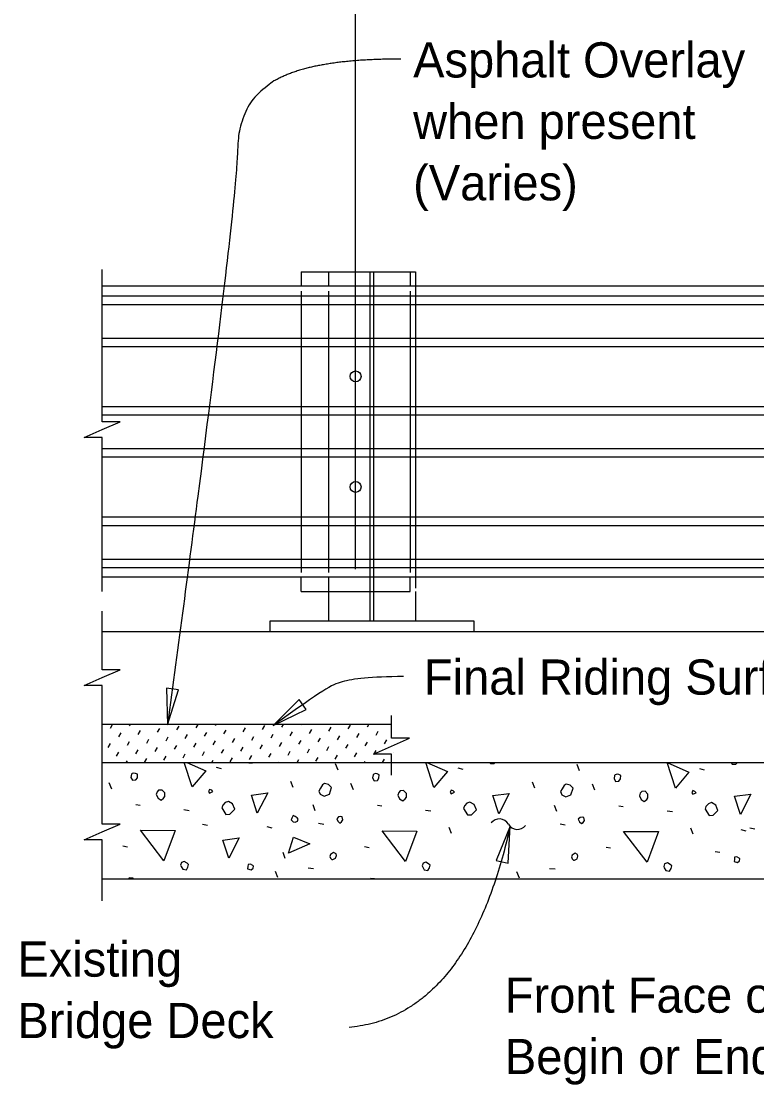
# Model space of a CAD drawing. Extents: x 21587 to 21659.1, y 56113.9 to 56155.9.
# Drawn here: x 21587.2 to 21591.41, y 56132.2 to 56138.3 of the extents above; entities that cross this region are included whole.
import ezdxf

# ---------------------------------------------------------------- set-up
doc = ezdxf.new("R2010")
doc.units = 0
for name, color, linetype in [('AdhocPoint_dp', 7, 'Continuous'), ('Border', 7, 'Continuous'), ('Patterning', 7, 'Continuous'), ('PlotBorder_dp', 7, 'Continuous'), ('SheetBorder_dp', 7, 'Continuous'), ('TextMisc', 7, 'Continuous')]:
    doc.layers.add(name, color=color, linetype=linetype)

msp = doc.modelspace()

# ---------------------------------------------------------------- linework, layer by layer
at = {"layer": 'AdhocPoint_dp'}
for p, q in [((21593.837, 56134.8009), (21587.6633, 56134.8009)), ((21589.3212, 56134.2699), (21587.6633, 56134.2699)), ((21587.6633, 56134.0511), (21593.837, 56134.0511)), ((21587.6633, 56133.3843), (21593.837, 56133.3843))]:
    msp.add_line(p, q, dxfattribs=at)
at = {"layer": 'Border'}
for p, q in [((21588.9596, 56136.8635), (21589.4596, 56136.8635)), ((21588.9596, 56136.8635), (21588.9596, 56136.7802)), ((21599.7592, 56136.7801), (21587.6633, 56136.7801)), ((21587.6633, 56136.7246), (21599.7592, 56136.7246)), ((21587.6633, 56136.6764), (21599.7592, 56136.6764)), ((21587.6633, 56136.4835), (21599.7592, 56136.4835)), ((21587.6633, 56136.4353), (21599.7592, 56136.4353)), ((21587.6633, 56136.0914), (21599.7592, 56136.0914)), ((21587.6633, 56136.0431), (21599.7592, 56136.0431)), ((21587.6633, 56135.8503), (21599.7592, 56135.8503)), ((21587.6633, 56135.8022), (21599.7592, 56135.8022)), ((21587.6633, 56135.4582), (21599.7592, 56135.4582)), ((21587.6633, 56135.41), (21599.7592, 56135.41)), ((21587.6633, 56135.2172), (21599.7592, 56135.2172)), ((21587.6633, 56135.169), (21599.7592, 56135.169)), ((21599.7592, 56135.1134), (21587.6633, 56135.1134)), ((21588.9596, 56135.1135), (21588.9596, 56134.8635)), ((21589.4596, 56135.0302), (21589.4596, 56134.8635)), ((21588.6263, 56134.8635), (21589.7929, 56134.8635)), ((21588.6263, 56134.801), (21588.6263, 56134.8635)), ((21588.9596, 56134.8635), (21589.4596, 56134.8635)), ((21589.7929, 56134.8635), (21589.7929, 56134.801)), ((21588.6263, 56134.801), (21589.7929, 56134.801))]:
    msp.add_line(p, q, dxfattribs=at)
for centre in [(21589.1159, 56136.2634), (21589.1159, 56135.6303)]:
    msp.add_circle(centre, 0.0312, dxfattribs=at)
at = {"layer": 'Patterning'}
for p, q in [((21589.1992, 56134.8635), (21589.1992, 56136.8635)), ((21589.22, 56134.8635), (21589.22, 56136.8635)), ((21589.4596, 56136.8635), (21589.4596, 56135.0505)), ((21588.9596, 56136.7516), (21588.9596, 56135.1398))]:
    msp.add_line(p, q, dxfattribs=at)
at = {"layer": 'PlotBorder_dp'}
msp.add_line((21589.1159, 56135.1581), (21589.1159, 56143.3113), dxfattribs=at)
for points in [[(21587.6633, 56135.0304), (21587.6633, 56135.9136), (21587.5599, 56135.9136), (21587.6633, 56135.9586), (21587.7666, 56136.0036), (21587.6633, 56136.0036), (21587.6633, 56136.8766)], [(21587.6633, 56134.023), (21587.6633, 56134.4931), (21587.5599, 56134.4931), (21587.6633, 56134.5381), (21587.7666, 56134.5831), (21587.6633, 56134.5831), (21587.6633, 56134.9176)], [(21589.3213, 56133.979), (21589.3213, 56134.0999), (21589.2179, 56134.0999), (21589.3213, 56134.1449), (21589.4246, 56134.1899), (21589.3213, 56134.1899), (21589.3213, 56134.3205)], [(21587.6633, 56133.2579), (21587.6633, 56133.6085), (21587.5599, 56133.6085), (21587.6633, 56133.6535), (21587.7666, 56133.6985), (21587.6633, 56133.6985), (21587.6633, 56134.023)]]:
    msp.add_lwpolyline(points, dxfattribs=at)
for points in [[(21588.0386, 56134.2665), (21588.1011, 56134.4682), (21588.0312, 56134.4775)], [(21588.6428, 56134.2633), (21588.8333, 56134.3544), (21588.7927, 56134.4121)], [(21590.0017, 56133.6862), (21589.922, 56133.4906), (21589.9908, 56133.4753)]]:
    msp.add_lwpolyline(points, close=True, dxfattribs=at)
for centre, start, end in [((21589.94, 56133.6681), 30.00813, 141.73535), ((21590.0432, 56133.7277), 210.00813, 321.73535)]:
    msp.add_arc(centre, 0.0596, start, end, dxfattribs=at)
for points, degree in [([(21589.3746, 56138.082), (21588.8608, 56138.082), (21588.4383, 56137.8307), (21588.4383, 56137.2595), (21588.0386, 56134.2665)], 2), ([(21589.3913, 56134.5436), (21589.1979, 56134.5415), (21589.0095, 56134.5211), (21588.9381, 56134.4713), (21588.6427, 56134.2634)], 3), ([(21590.0017, 56133.6862), (21589.758, 56132.5935), (21589.078, 56132.5336)], 2)]:
    msp.add_open_spline(points, degree=degree, dxfattribs=at)
at = {"layer": 'TextMisc'}
for p, q in [((21588.8034, 56136.8635), (21589.4284, 56136.8635)), ((21588.8034, 56136.8635), (21588.8034, 56136.7802)), ((21589.4284, 56136.8635), (21589.4284, 56136.7802)), ((21588.8034, 56136.7516), (21588.8034, 56135.1398)), ((21589.4284, 56136.7516), (21589.4284, 56135.1398)), ((21588.8034, 56135.0302), (21588.8034, 56135.1135)), ((21589.4284, 56135.0302), (21589.4284, 56135.1135)), ((21588.8034, 56135.0302), (21589.4284, 56135.0302)), ((21587.7102, 56134.2474), (21587.7231, 56134.2698)), ((21587.8208, 56134.2604), (21587.8263, 56134.2699)), ((21588.0909, 56134.2375), (21588.1039, 56134.2599)), ((21588.2015, 56134.2504), (21588.2128, 56134.2699)), ((21588.3122, 56134.2634), (21588.3159, 56134.2699)), ((21588.5823, 56134.2405), (21588.5952, 56134.2629)), ((21588.6929, 56134.2535), (21588.7024, 56134.2699)), ((21588.8035, 56134.2664), (21588.8055, 56134.2699)), ((21589.0736, 56134.2435), (21589.0866, 56134.2659)), ((21589.1843, 56134.2565), (21589.192, 56134.2699)), ((21589.2949, 56134.2695), (21589.2952, 56134.2699)), ((21587.759, 56134.1986), (21587.772, 56134.221)), ((21587.8696, 56134.2116), (21587.8826, 56134.234)), ((21587.9803, 56134.2245), (21587.9932, 56134.2469)), ((21588.1397, 56134.1887), (21588.1527, 56134.211)), ((21588.2504, 56134.2016), (21588.2633, 56134.224)), ((21588.361, 56134.2146), (21588.374, 56134.237)), ((21588.4716, 56134.2275), (21588.4846, 56134.2499)), ((21588.5205, 56134.1787), (21588.5334, 56134.2011)), ((21588.6311, 56134.1917), (21588.6441, 56134.2141)), ((21588.7417, 56134.2046), (21588.7547, 56134.227)), ((21588.8524, 56134.2176), (21588.8653, 56134.24)), ((21588.963, 56134.2306), (21588.976, 56134.253)), ((21589.0118, 56134.1817), (21589.0248, 56134.2041)), ((21589.1225, 56134.1947), (21589.1354, 56134.2171)), ((21589.2331, 56134.2077), (21589.2461, 56134.23)), ((21587.6972, 56134.1368), (21587.7102, 56134.1592)), ((21587.8078, 56134.1498), (21587.8208, 56134.1722)), ((21587.9185, 56134.1627), (21587.9314, 56134.1851)), ((21588.0291, 56134.1757), (21588.0421, 56134.1981)), ((21588.0779, 56134.1269), (21588.0909, 56134.1492)), ((21588.1886, 56134.1398), (21588.2015, 56134.1622)), ((21588.2992, 56134.1528), (21588.3122, 56134.1752)), ((21588.4098, 56134.1657), (21588.4228, 56134.1881)), ((21588.4587, 56134.1169), (21588.4716, 56134.1393)), ((21588.5693, 56134.1299), (21588.5823, 56134.1523)), ((21588.6799, 56134.1428), (21588.6929, 56134.1652)), ((21588.7906, 56134.1558), (21588.8035, 56134.1782)), ((21588.9012, 56134.1688), (21588.9142, 56134.1912)), ((21588.95, 56134.1199), (21588.963, 56134.1423)), ((21589.0607, 56134.1329), (21589.0736, 56134.1553)), ((21589.1713, 56134.1459), (21589.1843, 56134.1682)), ((21589.2819, 56134.1588), (21589.2949, 56134.1812)), ((21587.746, 56134.088), (21587.759, 56134.1104)), ((21587.8567, 56134.1009), (21587.8696, 56134.1233)), ((21587.9673, 56134.1139), (21587.9803, 56134.1363)), ((21588.0161, 56134.0651), (21588.0291, 56134.0874)), ((21588.1268, 56134.078), (21588.1397, 56134.1004)), ((21588.2374, 56134.091), (21588.2504, 56134.1134)), ((21588.348, 56134.1039), (21588.361, 56134.1263)), ((21588.3969, 56134.0551), (21588.4098, 56134.0775)), ((21588.5075, 56134.0681), (21588.5205, 56134.0905)), ((21588.6181, 56134.081), (21588.6311, 56134.1034)), ((21588.7288, 56134.094), (21588.7417, 56134.1164)), ((21588.8394, 56134.107), (21588.8524, 56134.1294)), ((21588.8882, 56134.0581), (21588.9012, 56134.0805)), ((21588.9989, 56134.0711), (21589.0118, 56134.0935)), ((21589.1095, 56134.0841), (21589.1225, 56134.1065)), ((21589.2201, 56134.097), (21589.2331, 56134.1194)), ((21589.3308, 56134.11), (21589.3309, 56134.1102)), ((21587.8017, 56134.0509), (21587.8078, 56134.0615)), ((21587.9055, 56134.0521), (21587.9185, 56134.0745)), ((21588.1882, 56134.0509), (21588.1886, 56134.0516)), ((21588.2913, 56134.0509), (21588.2992, 56134.0645)), ((21588.3168, 56134.0238), (21588.3451, 56134.0167)), ((21588.6778, 56134.0509), (21588.6799, 56134.0546)), ((21588.7809, 56134.0509), (21588.7906, 56134.0676)), ((21589.0151, 56134.0079), (21589.001, 56134.0432)), ((21589.1674, 56134.0509), (21589.1713, 56134.0576)), ((21589.2706, 56134.0509), (21589.2819, 56134.0706)), ((21589.7015, 56134.0203), (21589.7298, 56134.0132)), ((21590.3998, 56134.0043), (21590.3856, 56134.0397)), ((21591.0862, 56134.0167), (21591.1145, 56134.0096)), ((21587.7182, 56133.8989), (21587.7041, 56133.9343)), ((21588.7588, 56133.9071), (21588.7446, 56133.9425)), ((21589.1029, 56133.8954), (21589.0887, 56133.9307)), ((21590.1435, 56133.9036), (21590.1293, 56133.9389)), ((21590.4875, 56133.8918), (21590.4734, 56133.9272)), ((21587.8561, 56133.8105), (21587.8808, 56133.807)), ((21588.1319, 56133.7822), (21588.1619, 56133.7769)), ((21588.8843, 56133.7745), (21588.8719, 56133.8081)), ((21589.2408, 56133.807), (21589.2655, 56133.8034)), ((21589.5165, 56133.7787), (21589.5466, 56133.7734)), ((21590.269, 56133.771), (21590.2566, 56133.8046)), ((21590.6254, 56133.8034), (21590.6502, 56133.7999)), ((21590.9012, 56133.7752), (21590.9313, 56133.7699)), ((21588.2388, 56133.6983), (21588.2671, 56133.6913)), ((21588.6068, 56133.6844), (21588.635, 56133.6773)), ((21588.9031, 56133.7027), (21588.9332, 56133.6974)), ((21589.665, 56133.6443), (21589.6526, 56133.6779)), ((21590.2878, 56133.6991), (21590.3178, 56133.6938)), ((21591.0497, 56133.6408), (21591.0373, 56133.6744)), ((21591.3237, 56133.6673), (21591.352, 56133.6603)), ((21591.3761, 56133.6773), (21591.4044, 56133.6702)), ((21587.7818, 56133.5736), (21587.8083, 56133.5683)), ((21588.7128, 56133.5018), (21588.7004, 56133.5354)), ((21589.1665, 56133.5701), (21589.193, 56133.5648)), ((21590.5512, 56133.5666), (21590.5777, 56133.5613)), ((21591.177, 56133.5418), (21591.2035, 56133.5365)), ((21588.6704, 56133.3922), (21588.6563, 56133.4275)), ((21588.843, 56133.4481), (21588.8748, 56133.4446)), ((21590.0551, 56133.3886), (21590.0409, 56133.424)), ((21590.2277, 56133.4446), (21590.2595, 56133.4411))]:
    msp.add_line(p, q, dxfattribs=at)
for points in [[(21588.1796, 56133.9113), (21588.1341, 56134.0509)], [(21588.148, 56134.0509), (21588.2574, 56134.0032), (21588.1796, 56133.9113)], [(21588.5032, 56134.0509), (21588.5042, 56134.0485), (21588.5018, 56134.0509)], [(21588.5042, 56134.0485), (21588.5254, 56134.0485), (21588.5278, 56134.0509)], [(21589.5643, 56133.9077), (21589.5177, 56134.0509)], [(21589.5246, 56134.0509), (21589.642, 56133.9997), (21589.5643, 56133.9077)], [(21589.8864, 56134.0509), (21589.8889, 56134.045), (21589.8854, 56134.0485)], [(21589.8889, 56134.045), (21589.9101, 56134.045), (21589.9161, 56134.0509)], [(21590.9489, 56133.9042), (21590.9012, 56134.0509), (21591.0267, 56133.9961), (21590.9489, 56133.9042)], [(21591.2695, 56134.0509), (21591.2736, 56134.0415), (21591.27, 56134.045)], [(21591.2736, 56134.0415), (21591.2948, 56134.0415), (21591.3043, 56134.0509)], [(21587.8278, 56133.9661), (21587.8366, 56133.9502), (21587.8561, 56133.9519), (21587.8649, 56133.9643), (21587.8667, 56133.9838), (21587.8543, 56133.9891), (21587.8455, 56133.9908), (21587.8349, 56133.9873), (21587.8313, 56133.9838), (21587.8278, 56133.9661)], [(21589.2125, 56133.9625), (21589.2213, 56133.9466), (21589.2408, 56133.9484), (21589.2496, 56133.9608), (21589.2514, 56133.9802), (21589.239, 56133.9855), (21589.2302, 56133.9873), (21589.2195, 56133.9838), (21589.216, 56133.9802), (21589.2125, 56133.9625)], [(21590.5971, 56133.959), (21590.606, 56133.9431), (21590.6254, 56133.9449), (21590.6343, 56133.9572), (21590.636, 56133.9767), (21590.6237, 56133.982), (21590.6148, 56133.9838), (21590.6042, 56133.9802), (21590.6007, 56133.9767), (21590.5971, 56133.959)], [(21588.2786, 56133.8759), (21588.298, 56133.8848), (21588.291, 56133.8918), (21588.2786, 56133.8971), (21588.2733, 56133.8848), (21588.2786, 56133.8759)], [(21588.9126, 56133.87), (21588.9356, 56133.8576), (21588.9656, 56133.87), (21588.978, 56133.9071), (21588.9603, 56133.9248), (21588.9373, 56133.9301), (21588.9267, 56133.923), (21588.9143, 56133.9036), (21588.9055, 56133.8877), (21588.9126, 56133.87)], [(21590.2973, 56133.8665), (21590.3202, 56133.8541), (21590.3503, 56133.8665), (21590.3627, 56133.9036), (21590.345, 56133.9213), (21590.322, 56133.9266), (21590.3114, 56133.9195), (21590.299, 56133.9), (21590.2902, 56133.8841), (21590.2973, 56133.8665)], [(21587.9728, 56133.8671), (21587.9834, 56133.8459), (21588.001, 56133.8353), (21588.0152, 56133.8459), (21588.0222, 56133.8565), (21588.0222, 56133.8777), (21588.0063, 56133.8936), (21587.9869, 56133.8918), (21587.9781, 56133.883), (21587.9728, 56133.8671)], [(21588.552, 56133.7604), (21588.5184, 56133.8647), (21588.6121, 56133.8771), (21588.552, 56133.7604)], [(21589.3574, 56133.8635), (21589.368, 56133.8423), (21589.3857, 56133.8317), (21589.3999, 56133.8423), (21589.4069, 56133.8529), (21589.4069, 56133.8742), (21589.391, 56133.8901), (21589.3716, 56133.8883), (21589.3627, 56133.8795), (21589.3574, 56133.8635)], [(21589.6633, 56133.8724), (21589.6827, 56133.8812), (21589.6756, 56133.8883), (21589.6633, 56133.8936), (21589.6579, 56133.8812), (21589.6633, 56133.8724)], [(21589.9366, 56133.7569), (21589.903, 56133.8612), (21589.9967, 56133.8735), (21589.9366, 56133.7569)], [(21590.7421, 56133.86), (21590.7527, 56133.8388), (21590.7704, 56133.8282), (21590.7845, 56133.8388), (21590.7916, 56133.8494), (21590.7916, 56133.8706), (21590.7757, 56133.8865), (21590.7562, 56133.8848), (21590.7474, 56133.8759), (21590.7421, 56133.86)], [(21591.0479, 56133.8689), (21591.0674, 56133.8777), (21591.0603, 56133.8848), (21591.0479, 56133.8901), (21591.0426, 56133.8777), (21591.0479, 56133.8689)], [(21591.3213, 56133.7533), (21591.2877, 56133.8576), (21591.3814, 56133.87), (21591.3213, 56133.7533)], [(21588.3493, 56133.7911), (21588.3723, 56133.7539), (21588.3952, 56133.7557), (21588.4041, 56133.7646), (21588.4235, 56133.784), (21588.4112, 56133.814), (21588.3864, 56133.8282), (21588.3687, 56133.8211), (21588.3546, 56133.807), (21588.3493, 56133.7911)], [(21589.734, 56133.7875), (21589.7569, 56133.7504), (21589.7799, 56133.7522), (21589.7888, 56133.761), (21589.8082, 56133.7805), (21589.7958, 56133.8105), (21589.7711, 56133.8247), (21589.7534, 56133.8176), (21589.7393, 56133.8034), (21589.734, 56133.7875)], [(21591.1186, 56133.784), (21591.1416, 56133.7469), (21591.1646, 56133.7486), (21591.1734, 56133.7575), (21591.1929, 56133.7769), (21591.1805, 56133.807), (21591.1558, 56133.8211), (21591.1381, 56133.814), (21591.1239, 56133.7999), (21591.1186, 56133.784)], [(21588.7577, 56133.7114), (21588.7701, 56133.7096), (21588.7824, 56133.7149), (21588.786, 56133.7256), (21588.7807, 56133.7344), (21588.7701, 56133.7415), (21588.7577, 56133.7468), (21588.7506, 56133.7326), (21588.7471, 56133.722), (21588.7577, 56133.7114)], [(21589.0145, 56133.7151), (21589.0251, 56133.7044), (21589.0357, 56133.7115), (21589.0428, 56133.7221), (21589.0392, 56133.7398), (21589.0304, 56133.7416), (21589.018, 56133.7398), (21589.0074, 56133.7292), (21589.0145, 56133.7151)], [(21590.3992, 56133.7115), (21590.4098, 56133.7009), (21590.4204, 56133.708), (21590.4274, 56133.7186), (21590.4239, 56133.7363), (21590.4151, 56133.738), (21590.4027, 56133.7363), (21590.3921, 56133.7257), (21590.3992, 56133.7115)], [(21588.0169, 56133.487), (21587.8826, 56133.6638), (21588.0824, 56133.662), (21588.0169, 56133.487)], [(21589.4016, 56133.4835), (21589.2673, 56133.6603), (21589.467, 56133.6585), (21589.4016, 56133.4835)], [(21590.7863, 56133.4799), (21590.652, 56133.6567), (21590.8517, 56133.655), (21590.7863, 56133.4799)], [(21588.3887, 56133.5022), (21588.3551, 56133.6065), (21588.4488, 56133.6188), (21588.3887, 56133.5022)], [(21588.7316, 56133.5312), (21588.7599, 56133.6231), (21588.8536, 56133.586), (21588.7316, 56133.5312)], [(21588.9791, 56133.4959), (21588.9862, 56133.4959), (21589.0003, 56133.5029), (21589.0056, 56133.5188), (21589.0039, 56133.5277), (21588.9897, 56133.5347), (21588.9721, 56133.5241), (21588.9685, 56133.5135), (21588.9721, 56133.5029), (21588.9791, 56133.4959)], [(21590.3638, 56133.4923), (21590.3709, 56133.4923), (21590.385, 56133.4994), (21590.3903, 56133.5153), (21590.3886, 56133.5241), (21590.3744, 56133.5312), (21590.3567, 56133.5206), (21590.3532, 56133.51), (21590.3567, 56133.4994), (21590.3638, 56133.4923)], [(21588.1159, 56133.4552), (21588.1248, 56133.4393), (21588.146, 56133.4357), (21588.1548, 56133.4517), (21588.1584, 56133.4658), (21588.1495, 56133.4746), (21588.1336, 56133.4835), (21588.1177, 56133.4782), (21588.1124, 56133.4623), (21588.1159, 56133.4552)], [(21588.4968, 56133.4422), (21588.5163, 56133.4369), (21588.5286, 56133.4457), (21588.5304, 56133.4581), (21588.5269, 56133.4617), (21588.5127, 56133.4687), (21588.5003, 56133.467), (21588.4986, 56133.4546), (21588.4968, 56133.4422)], [(21589.5006, 56133.4517), (21589.5095, 56133.4357), (21589.5307, 56133.4322), (21589.5395, 56133.4481), (21589.543, 56133.4623), (21589.5342, 56133.4711), (21589.5183, 56133.4799), (21589.5024, 56133.4746), (21589.4971, 56133.4587), (21589.5006, 56133.4517)], [(21590.8853, 56133.4481), (21590.8941, 56133.4322), (21590.9153, 56133.4287), (21590.9242, 56133.4446), (21590.9277, 56133.4587), (21590.9189, 56133.4676), (21590.903, 56133.4764), (21590.8871, 56133.4711), (21590.8818, 56133.4552), (21590.8853, 56133.4481)], [(21591.2848, 56133.4835), (21591.3043, 56133.4782), (21591.3166, 56133.487), (21591.3184, 56133.4994), (21591.3149, 56133.5029), (21591.3007, 56133.51), (21591.2883, 56133.5082), (21591.2866, 56133.4959), (21591.2848, 56133.4835)], [(21587.8412, 56133.3843), (21587.8402, 56133.388), (21587.8172, 56133.3898), (21587.8154, 56133.3843)], [(21589.2249, 56133.3843), (21589.2248, 56133.3845), (21589.2019, 56133.3862), (21589.2012, 56133.3843)]]:
    msp.add_lwpolyline(points, dxfattribs=at)

# ---------------------------------------------------------------- texts
at = {"layer": 'PlotBorder_dp'}
for s, p in [('Asphalt Overlay', (21589.4456, 56137.9764)), ('when present', (21589.4456, 56137.6244)), ('(Varies)', (21589.4456, 56137.2724)), ('Existing ', (21587.1774, 56132.824)), ('Front Face of Backwall &', (21589.9713, 56132.6176)), ('Bridge Deck', (21587.1774, 56132.472)), ('Begin or End Bridge', (21589.9713, 56132.2656))]:
    msp.add_text(s, height=0.2016, dxfattribs=at).set_placement(p)
at = {"layer": 'SheetBorder_dp'}
msp.add_text('Final Riding Surface', height=0.2016, dxfattribs=at).set_placement((21589.5074, 56134.4399))

doc.saveas('drawing.dxf')
